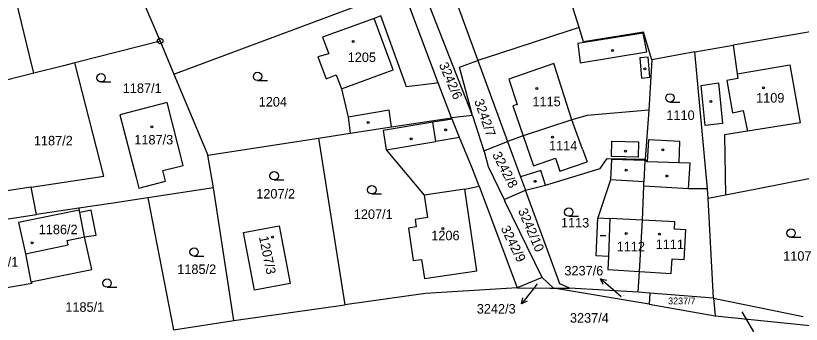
# Model space of a CAD drawing. Extents: x -736345 to -729997, y -1130177 to -1122501.
# Drawn here: x -734088.1 to -733947.7, y -1126601.7 to -1126546.6 of the extents above; entities that cross this region are included whole.
import ezdxf

# ---------------------------------------------------------------- set-up
doc = ezdxf.new("R2010")
doc.units = 0
for name, color, linetype in [('Vrstva 1', 7, 'Continuous'), ('Vrstva 16', 7, 'Continuous'), ('Vrstva 18', 7, 'Continuous'), ('Vrstva 19', 7, 'Continuous'), ('Vrstva 25', 7, 'Continuous'), ('Vrstva 4', 7, 'Continuous')]:
    doc.layers.add(name, color=color, linetype=linetype)

msp = doc.modelspace()

# ---------------------------------------------------------------- linework, layer by layer
at = {"layer": 'Vrstva 1'}
for points in [[(-733987.44, -1126548.69), (-733992.96, -1126531.12)], [(-734069.23, -1126535.01), (-734062.32, -1126551.12)], [(-734012.58, -1126535.36), (-734005.52, -1126554.62)], [(-734085.69, -1126553.72), (-734089.91, -1126536.2)], [(-734006.52, -1126564.43), (-734015.91, -1126540.4)], [(-734059.9, -1126557.06), (-734018.93, -1126541.75)], [(-734012.61, -1126558.59), (-734018.93, -1126541.75)], [(-734024.07, -1126547.08), (-734033.29, -1126550.45)], [(-734022.87, -1126546.64), (-734024.07, -1126547.08)], [(-734018.31, -1126559.3), (-734022.87, -1126546.64)], [(-733933.78, -1126547.31), (-733959.94, -1126551.89)], [(-733987.44, -1126548.69), (-733989.29, -1126549.3)], [(-733986.64, -1126551.24), (-733987.44, -1126548.69)], [(-733989.29, -1126549.3), (-734001.69, -1126553.37)], [(-733975.91, -1126549.57), (-733986.64, -1126551.24)], [(-733974.47, -1126554.46), (-733975.91, -1126549.57)], [(-734062.32, -1126551.12), (-734077.56, -1126555.01)], [(-734062.32, -1126551.12), (-734059.9, -1126557.06)], [(-734033.29, -1126550.45), (-734032.2, -1126553.41)], [(-733966.75, -1126553.08), (-733959.94, -1126551.89)], [(-733959.94, -1126551.89), (-733959.21, -1126556.97)], [(-734084.93, -1126556.89), (-734085.69, -1126553.72)], [(-734032.2, -1126553.41), (-734034.12, -1126553.97)], [(-734034.12, -1126553.97), (-734032.65, -1126557.87)], [(-734001.69, -1126553.37), (-734005.52, -1126554.62)], [(-733966.75, -1126553.08), (-733974.47, -1126554.46)], [(-733964.51, -1126577.54), (-733966.75, -1126553.08)], [(-734079.59, -1126555.53), (-734084.93, -1126556.89)], [(-734077.56, -1126555.01), (-734079.59, -1126555.53)], [(-734072.37, -1126575.26), (-734077.56, -1126555.01)], [(-734008.84, -1126555.81), (-734005.52, -1126554.62)], [(-734005.52, -1126554.62), (-734000.23, -1126569.05)], [(-733974.47, -1126554.46), (-733974.98, -1126563.49)], [(-733959.21, -1126556.97), (-733949.78, -1126555.4)], [(-733949.78, -1126555.4), (-733947.91, -1126565.76)], [(-734084.93, -1126556.89), (-734105.48, -1126562.13)], [(-734059.9, -1126557.06), (-734053.82, -1126571.48)], [(-734032.65, -1126557.87), (-734030.84, -1126557.15)], [(-734030.84, -1126557.15), (-734029.92, -1126559.67)], [(-734006.52, -1126564.43), (-734008.84, -1126555.81)], [(-734029.92, -1126559.67), (-734028.74, -1126564.72)], [(-734013.34, -1126558.68), (-734018.31, -1126559.3)], [(-734012.61, -1126558.59), (-734013.34, -1126558.68)], [(-734010.27, -1126564.83), (-734012.61, -1126558.59)], [(-734061.1, -1126562.12), (-734069.52, -1126564.28)], [(-734058.22, -1126573.34), (-734061.1, -1126562.12)], [(-733974.98, -1126563.49), (-733985.99, -1126564.4)], [(-733974.98, -1126563.49), (-733975.66, -1126572.2)], [(-734069.52, -1126564.28), (-734066.64, -1126575.5)], [(-734028.74, -1126564.72), (-734028.37, -1126567.6)], [(-734021, -1126566.47), (-734010.27, -1126564.83)], [(-734010.16, -1126565.1), (-734013.62, -1126565.62)], [(-734006.52, -1126564.43), (-734010.27, -1126564.83)], [(-734010.16, -1126565.1), (-734010.27, -1126564.83)], [(-734008.8, -1126568.38), (-734010.16, -1126565.1)], [(-734006.52, -1126564.43), (-734004.46, -1126570.75)], [(-733988.72, -1126565.18), (-733997.43, -1126568.06)], [(-733985.99, -1126564.4), (-733988.72, -1126565.18)], [(-734028.37, -1126567.6), (-734021, -1126566.47)], [(-734013.62, -1126565.62), (-734022.49, -1126567.09)], [(-733947.91, -1126565.76), (-733957.33, -1126567.22)], [(-734034.01, -1126568.46), (-734028.37, -1126567.6)], [(-734022.49, -1126567.09), (-734021.92, -1126570.55)], [(-734006.51, -1126573.93), (-734008.8, -1126568.38)], [(-733997.43, -1126568.06), (-734000.23, -1126569.05)], [(-733957.33, -1126567.22), (-733961.48, -1126567.86)], [(-733961.48, -1126567.86), (-733961.31, -1126578.66)], [(-734053.82, -1126571.48), (-734034.01, -1126568.46)], [(-734034.01, -1126568.46), (-734029.34, -1126598.26)], [(-734004.46, -1126570.75), (-734000.23, -1126569.05)], [(-734000.23, -1126569.05), (-733997.91, -1126575.38)], [(-733975.07, -1126568.78), (-733975.27, -1126572.71)], [(-733969.43, -1126569.06), (-733975.07, -1126568.78)], [(-733969.59, -1126572.86), (-733969.43, -1126569.06)], [(-734021.92, -1126570.55), (-734015.15, -1126578.64)], [(-734004.46, -1126570.75), (-734004.36, -1126571.04)], [(-734004.36, -1126571.04), (-734003.71, -1126573.56)], [(-734052.81, -1126577.36), (-734053.82, -1126571.48)], [(-733983.7, -1126573.9), (-733982.43, -1126572.12)], [(-733982.43, -1126572.12), (-733975.66, -1126572.2)], [(-733981.66, -1126572.27), (-733981.86, -1126575.94)], [(-733975.67, -1126572.45), (-733981.66, -1126572.27)], [(-733975.67, -1126572.45), (-733975.85, -1126576.27)], [(-733975.66, -1126572.2), (-733975.67, -1126572.45)], [(-733975.27, -1126572.71), (-733975.66, -1126572.2)], [(-734061.84, -1126574.27), (-734058.22, -1126573.34)], [(-734005.33, -1126577.07), (-734006.51, -1126573.93)], [(-734003.71, -1126573.56), (-734000.85, -1126579.44)], [(-733993.48, -1126576.87), (-733983.7, -1126573.9)], [(-733967.61, -1126572.94), (-733969.59, -1126572.86)], [(-733967.92, -1126577.53), (-733967.61, -1126572.94)], [(-734085.36, -1126577.22), (-734072.37, -1126575.26)], [(-734061.36, -1126576.16), (-734061.84, -1126574.27)], [(-733997.91, -1126575.38), (-733997.04, -1126577.78)], [(-734066.64, -1126575.5), (-734066.15, -1126577.39)], [(-734066.15, -1126577.39), (-734061.36, -1126576.16)], [(-733981.86, -1126575.94), (-733984.11, -1126582.7)], [(-733975.89, -1126577.05), (-733975.85, -1126576.27)], [(-733946.11, -1126575.69), (-733955.44, -1126577.51)], [(-734085.36, -1126577.22), (-734100.74, -1126579.53)], [(-734084.43, -1126582.12), (-734085.36, -1126577.22)], [(-734052.81, -1126577.36), (-734064.55, -1126579.13)], [(-734049.13, -1126601.05), (-734052.81, -1126577.36)], [(-734007.87, -1126577.56), (-734005.33, -1126577.07)], [(-734005.7, -1126592.15), (-734007.87, -1126577.56)], [(-734005.33, -1126577.07), (-733998.49, -1126595.22)], [(-734000.85, -1126579.44), (-733997.04, -1126577.78)], [(-733997.04, -1126577.78), (-733993.48, -1126576.87)], [(-733990.9, -1126594.46), (-733997.04, -1126577.78)], [(-733976.13, -1126583.11), (-733975.89, -1126577.05)], [(-733964.51, -1126577.54), (-733967.92, -1126577.53)], [(-733964.35, -1126579.26), (-733964.51, -1126577.54)], [(-733955.44, -1126577.51), (-733961.31, -1126578.66)], [(-734064.55, -1126579.13), (-734071.12, -1126580.12)], [(-734064.55, -1126579.13), (-734059.97, -1126602.69)], [(-734015.15, -1126578.64), (-734014.55, -1126582.64)], [(-734000.85, -1126579.44), (-734000.7, -1126579.75)], [(-733961.31, -1126578.66), (-733964.35, -1126579.26)], [(-733963.42, -1126597.04), (-733964.35, -1126579.26)], [(-734076.87, -1126580.98), (-734084.43, -1126582.12)], [(-734071.12, -1126580.12), (-734076.87, -1126580.98)], [(-734076.87, -1126580.98), (-734076.79, -1126581.35)], [(-733994.07, -1126593.33), (-734000.7, -1126579.75)], [(-734090.26, -1126583), (-734084.43, -1126582.12)], [(-734076.79, -1126581.35), (-734087.62, -1126583.55)], [(-734076.68, -1126581.76), (-734076.79, -1126581.35)], [(-734074.65, -1126581.35), (-734076.68, -1126581.76)], [(-734073.75, -1126585.78), (-734074.65, -1126581.35)], [(-734087.62, -1126583.55), (-734086.39, -1126589.11)], [(-734014.55, -1126582.64), (-734016.75, -1126582.98)], [(-734016.75, -1126582.98), (-734016.54, -1126584.32)], [(-733984.37, -1126589.49), (-733984.11, -1126582.7)], [(-733976.67, -1126592.3), (-733976.13, -1126583.11)], [(-734047.41, -1126585.32), (-734041.04, -1126584.14)], [(-734041.04, -1126584.14), (-734039.1, -1126594.43)], [(-734016.54, -1126584.32), (-734017.95, -1126584.54)], [(-734017.95, -1126584.54), (-734017.08, -1126590.33)], [(-734075.83, -1126586.08), (-734073.75, -1126585.78)], [(-734074.55, -1126591.92), (-734075.83, -1126586.08)], [(-734045.45, -1126595.62), (-734047.41, -1126585.32)], [(-734086.39, -1126589.11), (-734085.47, -1126594.13)], [(-734017.08, -1126590.33), (-734015.6, -1126590.11)], [(-734015.6, -1126590.11), (-734015.08, -1126593.55)], [(-733982.2, -1126589.59), (-733984.37, -1126589.49)], [(-733982.2, -1126589.59), (-733982.3, -1126591.95)], [(-734085.47, -1126594.13), (-734074.55, -1126591.92)], [(-734015.08, -1126593.55), (-734005.7, -1126592.15)], [(-733982.3, -1126591.95), (-733976.67, -1126592.3)], [(-733994.07, -1126593.33), (-733998.49, -1126595.22)], [(-733994.07, -1126593.33), (-733992.04, -1126595.24)], [(-733976.89, -1126596), (-733976.67, -1126592.3)], [(-734096.05, -1126596.19), (-734085.22, -1126594.38)], [(-734085.22, -1126594.38), (-734085.47, -1126594.13)], [(-734039.1, -1126594.43), (-734045.45, -1126595.62)], [(-733989.17, -1126595.25), (-733990.9, -1126594.46)], [(-734014.88, -1126596.22), (-734029.34, -1126598.26)], [(-733998.49, -1126595.22), (-734014.88, -1126596.22)], [(-733998.49, -1126595.22), (-733992.6, -1126595.24)], [(-733992.6, -1126595.24), (-733992.04, -1126595.24)], [(-733992.04, -1126595.24), (-733989.17, -1126595.25)], [(-733974.9, -1126598.13), (-733992.04, -1126595.24)], [(-733976.89, -1126596), (-733989.17, -1126595.25)], [(-733974.82, -1126596.16), (-733976.89, -1126596)], [(-733974.82, -1126596.16), (-733974.9, -1126598.13)], [(-733963.42, -1126597.04), (-733974.82, -1126596.16)], [(-733963.42, -1126597.04), (-733947.37, -1126600.32)], [(-733963.42, -1126597.04), (-733963.14, -1126600.17)], [(-734049.13, -1126601.05), (-734029.34, -1126598.26)], [(-733974.9, -1126598.13), (-733963.14, -1126600.17)], [(-733963.14, -1126600.17), (-733943.8, -1126602.19)], [(-734059.97, -1126602.69), (-734049.13, -1126601.05)]]:
    msp.add_lwpolyline(points, dxfattribs=at)
at = {"layer": 'Vrstva 16'}
for points in [[(-733994.94, -1126594.5), (-733995.89, -1126595.72)], [(-733979.93, -1126596.78), (-733981.34, -1126595.55)], [(-733958.35, -1126599.47), (-733957.76, -1126600.49)]]:
    msp.add_lwpolyline(points, dxfattribs=at)
at = {"layer": 'Vrstva 25'}
for points in [[(-734072.88, -1126558.44), (-734071.13, -1126558.44)], [(-734044.92, -1126558.2), (-734043.17, -1126558.2)], [(-733971.21, -1126562.04), (-733969.46, -1126562.04)], [(-734041.95, -1126575.94), (-734040.2, -1126575.94)], [(-734024.49, -1126578.44), (-734022.74, -1126578.44)], [(-733989.3, -1126582.42), (-733987.55, -1126582.42)], [(-733983.67, -1126585.87), (-733982.67, -1126585.87)], [(-733949.56, -1126586.18), (-733947.81, -1126586.18)], [(-734056.26, -1126589.55), (-734054.51, -1126589.55)], [(-733981.34, -1126595.55), (-733983.597, -1126593.574)], [(-733983.174, -1126594.609), (-733983.597, -1126593.574), (-733982.515, -1126593.857)], [(-734071.81, -1126595.1), (-734070.06, -1126595.1)], [(-733995.89, -1126595.72), (-733997.736, -1126598.084)], [(-733996.727, -1126597.603), (-733997.736, -1126598.084), (-733997.515, -1126596.988)], [(-733957.76, -1126600.49), (-733956.256, -1126603.085)]]:
    msp.add_lwpolyline(points, dxfattribs=at)
for centre, radius in [((-734062.32, -1126551.12), 0.5), ((-734062.32, -1126551.12), 0.032), ((-734027.81, -1126551.21), 0.175), ((-733981.49, -1126552.83), 0.175), ((-734072.88, -1126557.69), 0.75), ((-734044.92, -1126557.45), 0.75), ((-733975.71, -1126556.11), 0.175), ((-733995, -1126559.6), 0.175), ((-733954.47, -1126559.5), 0.175), ((-733971.21, -1126561.29), 0.75), ((-733963.92, -1126561.91), 0.175), ((-734025.16, -1126565.68), 0.175), ((-734063.8, -1126566.44), 0.175), ((-734011.3, -1126567), 0.175), ((-734017.44, -1126568.57), 0.175), ((-733992.18, -1126568.3), 0.175), ((-733979.15, -1126570.77), 0.175), ((-733972.47, -1126570.56), 0.175), ((-733979.06, -1126574.17), 0.175), ((-734041.95, -1126575.19), 0.75), ((-733971.78, -1126575.23), 0.175), ((-733995.28, -1126576.18), 0.175), ((-734024.49, -1126577.69), 0.75), ((-733989.3, -1126581.67), 0.75), ((-734011.78, -1126584.61), 0.175), ((-733949.56, -1126585.43), 0.75), ((-734042.23, -1126586.14), 0.175), ((-733979.06, -1126585.5), 0.175), ((-733973.09, -1126585.62), 0.175), ((-734085.19, -1126587.14), 0.175), ((-734056.26, -1126588.8), 0.75), ((-734071.81, -1126594.35), 0.75)]:
    msp.add_circle(centre, radius, dxfattribs=at)
at = {"layer": 'Vrstva 4'}
for points in [[(-734020.69, -1126556.24), (-734024.07, -1126547.08)], [(-733975.97, -1126549.74), (-733987.66, -1126551.58)], [(-733975.35, -1126553.07), (-733975.97, -1126549.74)], [(-733987.66, -1126551.58), (-733987.26, -1126555.01)], [(-733987.26, -1126555.01), (-733975.35, -1126553.07)], [(-733975.12, -1126554.01), (-733976.62, -1126554.13)], [(-733976.62, -1126554.13), (-733976.29, -1126557.77)], [(-733974.81, -1126557.6), (-733975.12, -1126554.01)], [(-733991.95, -1126555.15), (-734000.02, -1126557.94)], [(-733988.72, -1126565.18), (-733991.95, -1126555.15)], [(-734029.92, -1126559.67), (-734020.69, -1126556.24)], [(-733959.21, -1126556.97), (-733959.06, -1126557.83)], [(-734000.02, -1126557.94), (-733998.54, -1126562.43)], [(-733976.29, -1126557.77), (-733974.81, -1126557.6)], [(-733959.06, -1126557.83), (-733961.06, -1126558.18)], [(-733961.06, -1126558.18), (-733960.03, -1126563.92)], [(-733965.65, -1126559.08), (-733962.55, -1126558.6)], [(-733964.9, -1126566.18), (-733965.65, -1126559.08)], [(-733962.55, -1126558.6), (-733961.83, -1126565.88)], [(-733998.54, -1126562.43), (-733999.27, -1126562.7)], [(-733999.27, -1126562.7), (-733997.43, -1126568.06)], [(-734021.41, -1126563.5), (-734028.74, -1126564.72)], [(-734021, -1126566.47), (-734021.41, -1126563.5)], [(-733960.03, -1126563.92), (-733958.12, -1126563.51)], [(-733958.12, -1126563.51), (-733957.33, -1126567.22)], [(-733986.82, -1126570.43), (-733988.72, -1126565.18)], [(-734013.04, -1126569.09), (-734013.62, -1126565.62)], [(-733961.83, -1126565.88), (-733964.9, -1126566.18)], [(-734008.8, -1126568.38), (-734013.04, -1126569.09)], [(-733997.43, -1126568.06), (-733995.58, -1126573.42)], [(-734021.92, -1126570.55), (-734013.04, -1126569.09)], [(-733981.63, -1126571.74), (-733981.57, -1126569.03)], [(-733981.57, -1126569.03), (-733976.84, -1126569.14)], [(-733976.84, -1126569.14), (-733976.91, -1126571.85)], [(-733986.82, -1126570.43), (-733986.01, -1126572.67)], [(-733995.58, -1126573.42), (-733991.68, -1126572.07)], [(-733991.68, -1126572.07), (-733990.89, -1126574.35)], [(-733976.91, -1126571.85), (-733981.63, -1126571.74)], [(-733990.89, -1126574.35), (-733986.01, -1126572.67)], [(-733969.59, -1126572.86), (-733975.27, -1126572.71)], [(-733994.28, -1126574.26), (-733997.91, -1126575.38)], [(-733993.48, -1126576.87), (-733994.28, -1126574.26)], [(-733975.85, -1126576.27), (-733981.86, -1126575.94)], [(-734007.87, -1126577.56), (-734015.15, -1126578.64)], [(-733967.92, -1126577.53), (-733975.89, -1126577.05)], [(-734075.83, -1126586.08), (-734076.68, -1126581.76)], [(-733984.11, -1126582.7), (-733981.95, -1126582.81)], [(-733981.95, -1126582.81), (-733982.2, -1126589.59)], [(-733976.13, -1126583.11), (-733981.95, -1126582.81)], [(-733970.31, -1126583.4), (-733976.13, -1126583.11)], [(-733970.39, -1126584.75), (-733970.31, -1126583.4)], [(-733968.4, -1126584.87), (-733970.39, -1126584.75)], [(-733968.66, -1126590.15), (-733968.4, -1126584.87)], [(-734078.92, -1126586.73), (-734075.83, -1126586.08)], [(-734086.39, -1126589.11), (-734078.75, -1126587.52)], [(-734078.75, -1126587.52), (-734078.92, -1126586.73)], [(-733971.01, -1126592.66), (-733970.81, -1126590.04)], [(-733970.81, -1126590.04), (-733968.66, -1126590.15)], [(-733976.67, -1126592.3), (-733971.01, -1126592.66)]]:
    msp.add_lwpolyline(points, dxfattribs=at)

# ---------------------------------------------------------------- texts
at = {"layer": 'Vrstva 16'}
for s, p in [('3237/6', (-733990.077, -1126592.99)), ('3242/3', (-734005.737, -1126599.79))]:
    msp.add_text(s, height=1.7, dxfattribs=at).set_placement(p)
at = {"layer": 'Vrstva 18'}
for s, height, rotation, p in [('3242/6', 1.7, 293.20233, (-734012.538, -1126555.355)), ('3242/7', 1.7, 289.5023, (-734006.215, -1126561.831)), ('3242/8', 1.7, 297.50237, (-734003.021, -1126571.415)), ('3242/10', 1.7, 293.10233, (-733998.398, -1126581.405)), ('3242/9', 1.7, 296.50236, (-734001.502, -1126584.589)), ('3237/8', 0.1, 355.10282, (-733958.134, -1126599.288))]:
    msp.add_text(s, height=height, rotation=rotation, dxfattribs=at).set_placement(p)
for s, height, p in [('1187/1', 1.7, (-734069.01, -1126560.4)), ('1204', 1.7, (-734044.72, -1126562.82)), ('1110', 1.7, (-733971.85, -1126565.22)), ('1187/2', 1.7, (-734084.9, -1126569.76)), ('1207/2', 1.7, (-734045.158, -1126579.25)), ('1207/1', 1.7, (-734027.718, -1126582.9)), ('1113', 1.7, (-733990.69, -1126584.42)), ('1107', 1.7, (-733950.97, -1126590.36)), ('1185/2', 1.7, (-734059.27, -1126592.73)), ('3242/3', 0.1, (-733994.74, -1126594.3)), ('3237/6', 0.1, (-733979.73, -1126596.58)), ('1185/1', 1.7, (-734079.28, -1126599.48)), ('3237/7', 1.2, (-733971.54, -1126598.13)), ('3237/4', 1.7, (-733989.09, -1126601.42))]:
    msp.add_text(s, height=height, dxfattribs=at).set_placement(p)
at = {"layer": 'Vrstva 19'}
for s, p in [('1205', (-734028.81, -1126554.87)), ('1115', (-733995.79, -1126562.78)), ('1109', (-733955.81, -1126562.12)), ('1187/3', (-734066.95, -1126569.59)), ('1114', (-733992.83, -1126570.66)), ('1186/2', (-734084.03, -1126585.62)), ('1206', (-734013.87, -1126586.7)), ('1111', (-733973.76, -1126588.28)), ('1112', (-733980.73, -1126588.66)), ('1186/1', (-734094.63, -1126591.4))]:
    msp.add_text(s, height=1.7, dxfattribs=at).set_placement(p)
msp.add_text('1207/3', height=1.7, rotation=281.70224, dxfattribs=at).set_placement((-734044.683, -1126586.113))

doc.saveas('drawing.dxf')
